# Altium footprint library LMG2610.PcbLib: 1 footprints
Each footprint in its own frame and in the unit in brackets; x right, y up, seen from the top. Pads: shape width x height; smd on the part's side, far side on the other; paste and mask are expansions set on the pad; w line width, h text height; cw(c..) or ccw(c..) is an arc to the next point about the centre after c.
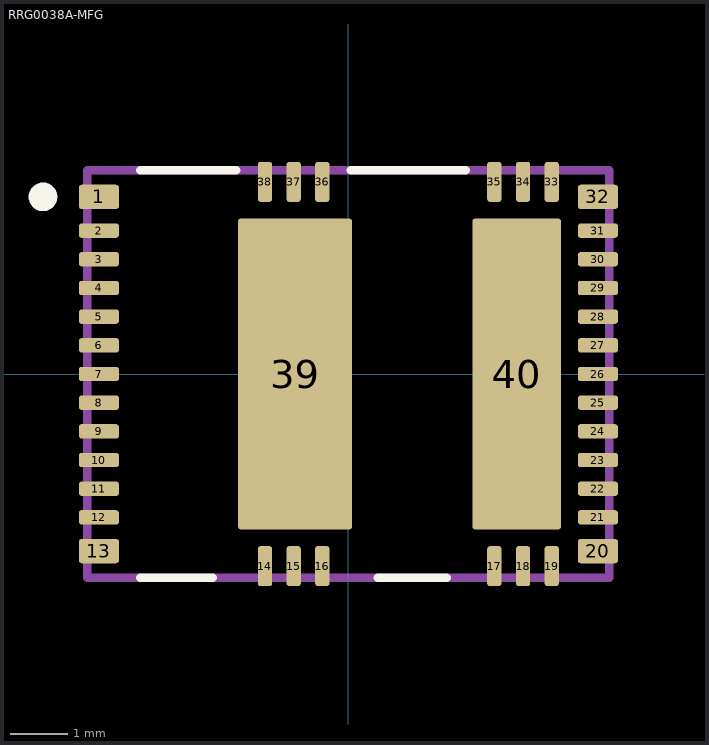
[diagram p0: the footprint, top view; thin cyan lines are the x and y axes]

## RRG0038A-MFG [mm]
pads (40):
  rrect24% 0.7x0.425 smd paste+0 mask-1000: 1(-4.35,3.087) 13(-4.35,-3.087) 20(4.35,-3.087) 32(4.35,3.087)
  rrect40% 0.7x0.25 smd paste+0 mask+0: 2(-4.35,2.5) 3(-4.35,2) 4(-4.35,1.5) 5(-4.35,1) 6(-4.35,0.5) 7(-4.35,0) 8(-4.35,-0.5) 9(-4.35,-1) 10(-4.35,-1.5) 11(-4.35,-2) 12(-4.35,-2.5) 21(4.35,-2.5) 22(4.35,-2) 23(4.35,-1.5) 24(4.35,-1) 25(4.35,-0.5) 26(4.35,0)
  rrect40% 0.25x0.7 smd paste+0 mask-1000: 14(-1.455,-3.35) 17(2.545,-3.35) 33(3.545,3.35) 34(3.045,3.35) 35(2.545,3.35) 36(-0.455,3.35) 37(-0.955,3.35) 38(-1.455,3.35)
  rrect40% 0.25x0.7 smd paste+0 mask+0: 15(-0.955,-3.35) 16(-0.455,-3.35) 18(3.045,-3.35) 19(3.545,-3.35)
  rrect40% 0.7x0.25 smd paste+0 mask-1000: 27(4.35,0.5) 28(4.35,1) 29(4.35,1.5) 30(4.35,2) 31(4.35,2.5)
  rrect5% 1.99x5.42 smd paste-1000 mask+0: 39(-0.93,0)
  rrect6% 1.55x5.42 smd paste-1000 mask+0: 40(2.935,0)
Top Overlay:
  circle w0.25: c-5.325,3.087 r0.125
  lines w0.15: -3.625,-3.55 -2.37,-3.55 ; -3.625,3.55 -1.955,3.55 ; 0.045,3.55 2.045,3.55 ; 0.51,-3.55 1.715,-3.55
Top Paste:
  drawing of 8 lines, arcs and shapes, not listed
Top Solder:
  drawing of 17 lines, arcs and shapes, not listed
Mechanical 5:
  lines w0.15: -4.55,-3.55 -4.55,3.55 4.55,3.55 4.55,-3.55 -4.55,-3.55
  text ".Designator" at 0.05,0.182 h0.5
3D body "IC_LMG2610RRGT_VQFN38.STEP": height 0.25, standoff 0, extent -4.87,-3.87 4.87,3.8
